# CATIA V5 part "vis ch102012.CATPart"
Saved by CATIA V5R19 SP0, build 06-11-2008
Part number: vis CH102010
Bounding box of the stored display mesh (mm): x 0 to 12, y -1.9 to 1.9, z -1.9 to 1.9
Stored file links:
  G:\project guitar elect\vis ch102012.CATPart
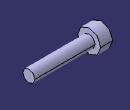
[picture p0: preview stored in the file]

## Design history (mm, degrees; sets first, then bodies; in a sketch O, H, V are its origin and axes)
Body1 (main body)
  Sketch1 on yz-plane, origin (0, 0, 0), H (0, 1, 0), V (0, 0, 1)
    circle A1 centre (0, 0) radius 1.9
    radius A1 = 1.9
  Pad1: profile Sketch1, direction (1, 0, 0), length 2
  Sketch2 on end face of Pad1, origin (2, 0, 0), H (0, 1, 0), V (0, 0, 1)
    circle A1 centre (0, 0) radius 1
    radius A1 = 1
  Pad2: profile Sketch2, direction (1, 0, 0), length 10
  Sketch3 on start face of Pad1, origin (0, 0, 0), H (0, -1, 0), V (0, 0, 1)
    axis line L1 (0, 1.0166) -> (0, -1.3601)
    point P1 (0, 1.0166)
    point P3 (0.5398, 0.5207)
    line L2 (0.5398, 0.5207) -> (0.5398, -0.5207)
    point P4 (0.5398, -0.5207)
    line L3 (0.5398, -0.5207) -> (0, -0.75)
    point P5 (0, -0.75)
    point P6 (0.5398, 0.5207)
    line L4 (0.5398, 0.5207) -> (0, 0.75)
    point P7 (0, 0.75)
    point P8 (-0.5398, -0.5207)
    point P9 (-0.5398, 0.5207)
    line L5 (-0.5398, 0.5207) -> (-0.5398, -0.5207)
    point P10 (0, 0.75)
    point P11 (-0.5398, 0.5207)
    line L6 (-0.5398, 0.5207) -> (0, 0.75)
    point P12 (0, -0.75)
    line L7 (-0.5398, -0.5207) -> (0, -0.75)
    coincidence: P1 V, P5 L1, P7 L1, P3 P6, P5 P12, P7 P10, P9 P11
    vertical: L1 V, L2 V
    symmetry: P4 P8 L1, P3 P9 L1, L2 L5 L1, P7 P10 L1, P6 P11 L1, L4 L6 L1, P5 P12 L1, L3 L7 L1
  Pocket1: profile Sketch3, direction (1, 0, 0), length 1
